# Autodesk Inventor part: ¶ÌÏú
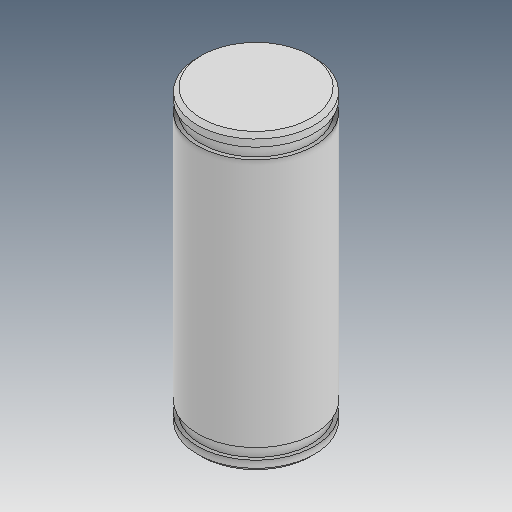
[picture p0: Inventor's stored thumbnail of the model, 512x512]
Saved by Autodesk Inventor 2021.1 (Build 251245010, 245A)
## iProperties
Created: 2019-05
Part Number: ¶ÌÏú
Material: Ogólny
Document SubType Name: Modeling
Designer: user
Density: 1 g/cm^3
Appearance: Domyślna
Author: user
Revision Number: ÈÎºÎ
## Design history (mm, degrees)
feature "ÊäÈë1"
node "Bryła1"
